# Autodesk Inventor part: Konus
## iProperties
Author: Bonse
Created: 2003-09
Part Number: Konus
Material: 1.0037
Document SubType Name: Blech
Designer: Bonse
Control State: 0
Master: False
Checked Out: False
PropertySet Name: Design Tracking Control
Shininess: 20.0
Angle Display Precision: 2
Document Length Units: 11269
Document Angle Units: 11283
Document Time Units: 11279
Document Mass Units: 11290
Document Length Units Precision: 3
Document Angle Units Precision: 2
Compacted: False
PropertySet Name: _Private Model Information
Density: 0.0
Volumn: 0.0
Area: 0.0
PropertySet Name: Model Information
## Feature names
1. Drehung1 [Revolution]
2. Extrusion2
